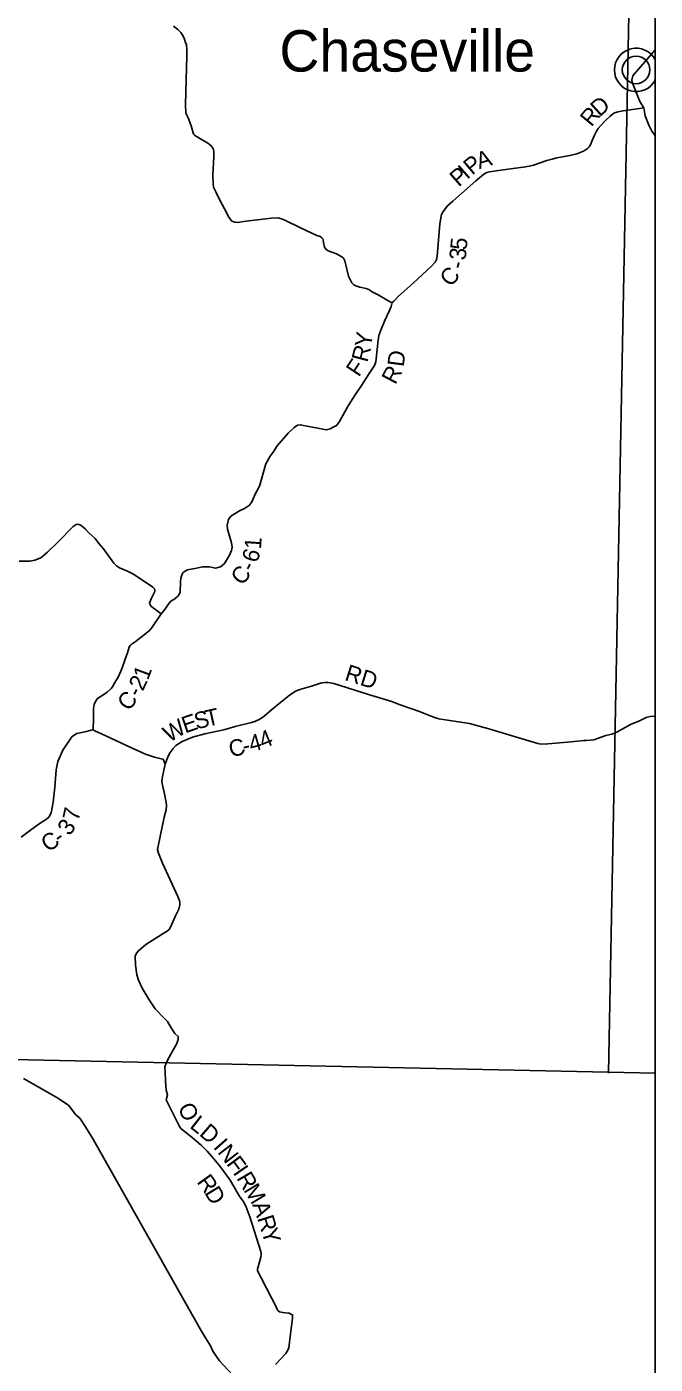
# Model space of a CAD drawing. Extents: x 0 to 34, y 0 to 22.
# Drawn here: x 28.547 to 30.697, y 13.16 to 17.734 of the extents above; entities that cross this region are included whole.
import ezdxf

# ---------------------------------------------------------------- set-up
doc = ezdxf.new("R2010")
doc.units = 0
for name, color, linetype in [('Default', 7, 'Continuous'), ('GM_X_County_Road', 7, 'Continuous'), ('GM_X_County_Road_Text', 7, 'Continuous'), ('GM_X_State_Route', 7, 'Continuous'), ('GM_X_Township', 7, 'Continuous'), ('GM_X_Unincorporated', 7, 'Continuous'), ('GM_X_Unincorporated_Text', 7, 'Continuous')]:
    doc.layers.add(name, color=color, linetype=linetype)

msp = doc.modelspace()

# ---------------------------------------------------------------- linework, layer by layer
at = {"layer": 'Default'}
msp.add_line((30.697, 20.4625), (30.697, 9.6182), dxfattribs=at)
for points in [[(30.6575, 17.4567), (30.6273, 17.4526), (30.6037, 17.4487), (30.587, 17.4467), (30.5689, 17.4432), (30.5547, 17.4384), (30.5425, 17.4286), (30.5266, 17.4132), (30.5109, 17.3964), (30.5021, 17.3859), (30.4947, 17.3746), (30.4889, 17.3637), (30.4815, 17.3453), (30.4749, 17.3302), (30.471, 17.3234), (30.4656, 17.3171), (30.4511, 17.3082), (30.4291, 17.299), (30.4051, 17.2936), (30.3733, 17.288), (30.36, 17.2855), (30.3441, 17.2811), (30.3266, 17.2768), (30.281, 17.2611), (30.2711, 17.2582), (30.2529, 17.2547), (30.1684, 17.2436), (30.1301, 17.2381), (30.1203, 17.2359), (30.11, 17.2304), (30.0832, 17.2069), (30.0047, 17.1378), (29.9863, 17.121), (29.9717, 17.1026), (29.9659, 17.0917), (29.9631, 17.0808), (29.9598, 17.0593), (29.957, 17.0191), (29.9504, 16.9492), (29.9488, 16.9382), (29.9437, 16.9284), (29.9318, 16.9153), (29.869, 16.8574), (29.8384, 16.8302), (29.8182, 16.8126), (29.8028, 16.7955), (29.7967, 16.7913), (29.7922, 16.7923), (29.7796, 16.7995), (29.7486, 16.817), (29.7264, 16.8282), (29.7189, 16.834), (29.708, 16.8383), (29.6865, 16.8431), (29.6729, 16.8482), (29.6654, 16.8517), (29.6591, 16.8583), (29.6472, 16.8807), (29.6347, 16.9339), (29.6303, 16.9431), (29.625, 16.9473), (29.607, 16.9574), (29.5784, 16.968), (29.5709, 16.9726), (29.566, 16.9799), (29.5625, 16.9958), (29.5614, 17.0045), (29.5592, 17.0091), (29.5566, 17.0126), (29.5502, 17.0164), (29.5397, 17.0196), (29.4837, 17.0468), (29.4303, 17.0729), (29.4186, 17.0776), (29.4062, 17.0804), (29.3827, 17.0796), (29.2974, 17.0693), (29.2663, 17.0648), (29.2588, 17.0652), (29.249, 17.0695), (29.2442, 17.0749), (29.2378, 17.0826), (29.2234, 17.1115), (29.2076, 17.1409), (29.1943, 17.1676), (29.1862, 17.1855), (29.1841, 17.1976), (29.1837, 17.2268), (29.1864, 17.29), (29.187, 17.307), (29.1852, 17.3139), (29.183, 17.3192), (29.1778, 17.3272), (29.1658, 17.3353), (29.1298, 17.357), (29.1223, 17.362), (29.1185, 17.3658), (29.1159, 17.3708), (29.1098, 17.3947), (29.1051, 17.4073), (29.0988, 17.4229), (29.0929, 17.4339), (29.0915, 17.4389), (29.0903, 17.4684), (29.0948, 17.635), (29.0946, 17.6426), (29.0943, 17.6562), (29.0937, 17.6725), (29.0904, 17.6805), (29.0864, 17.6915), (29.0805, 17.7037), (29.0735, 17.7144), (29.0634, 17.7248), (29.0488, 17.7363)], [(29.0798, 15.8643), (29.0799, 15.8645), (29.0807, 15.8664), (29.0868, 15.8706), (29.0969, 15.8763), (29.1279, 15.883), (29.1476, 15.8869), (29.1726, 15.8867), (29.193, 15.8827), (29.2097, 15.887), (29.2232, 15.898), (29.2408, 15.9266), (29.2471, 15.9425), (29.2501, 15.9547), (29.2477, 15.969), (29.2341, 16.0163), (29.2325, 16.0299), (29.2365, 16.0489), (29.2455, 16.0603), (29.2742, 16.0783), (29.2915, 16.086), (29.3085, 16.0982), (29.3171, 16.1093), (29.3283, 16.1355), (29.3432, 16.1628), (29.365, 16.2387), (29.3799, 16.265), (29.3897, 16.2787), (29.4039, 16.3004), (29.4407, 16.3446), (29.4621, 16.364), (29.4731, 16.3717), (29.4825, 16.3729), (29.5178, 16.3659), (29.5423, 16.3612), (29.5712, 16.3553), (29.5852, 16.3584), (29.5954, 16.365), (29.6067, 16.37), (29.6164, 16.384), (29.646, 16.4376), (29.6707, 16.4749), (29.6916, 16.5076), (29.7178, 16.5484), (29.7362, 16.5757), (29.7407, 16.5883), (29.7496, 16.6618), (29.7514, 16.6781), (29.758, 16.6967), (29.7707, 16.7267), (29.7882, 16.7636), (29.793, 16.7772), (29.7967, 16.7913)], [(28.5215, 15.9069), (28.557, 15.9064), (28.574, 15.9094), (28.5946, 15.9177), (28.6181, 15.9374), (28.6534, 15.9717), (28.7054, 16.0253), (28.7162, 16.0319), (28.7219, 16.0324), (28.7318, 16.0299), (28.7475, 16.0162), (28.7595, 16.0035), (28.7804, 15.9839), (28.7938, 15.967), (28.8095, 15.9485), (28.845, 15.8992), (28.8538, 15.8902), (28.8641, 15.8834), (28.891, 15.8719), (28.9005, 15.8678), (28.9115, 15.8622), (28.9781, 15.8176), (28.9838, 15.8115), (28.9854, 15.807), (28.9847, 15.8021), (28.9723, 15.7774), (28.9671, 15.7633), (28.9679, 15.7592), (28.9741, 15.7505), (28.9744, 15.7502)], [(29.0064, 15.7261), (29.0188, 15.7413), (29.033, 15.7615), (29.0398, 15.7691), (29.053, 15.7779), (29.0631, 15.786), (29.0688, 15.7924), (29.0717, 15.8), (29.073, 15.836), (29.0744, 15.8482), (29.077, 15.858), (29.0798, 15.8643)], [(28.9744, 15.7502), (28.9748, 15.7499), (29.0064, 15.7261), (28.9974, 15.7128), (28.9828, 15.6907), (28.9738, 15.6774), (28.9682, 15.6709), (28.949, 15.6541), (28.9174, 15.6308), (28.9038, 15.6212), (28.9008, 15.6182), (28.8971, 15.6125), (28.8915, 15.5931), (28.8822, 15.5673), (28.8737, 15.5415), (28.8693, 15.5305), (28.8592, 15.51), (28.8483, 15.4917), (28.8405, 15.4769), (28.836, 15.4708), (28.8225, 15.4586), (28.8066, 15.4486), (28.7957, 15.441), (28.7878, 15.4352), (28.7826, 15.4261), (28.7777, 15.4158), (28.7755, 15.4022), (28.7758, 15.3692), (28.7746, 15.3291), (28.7799, 15.3261), (28.8171, 15.3089), (28.9056, 15.2679), (28.9535, 15.2463), (28.9834, 15.2359), (29.0069, 15.2304), (29.0134, 15.2289), (29.0207, 15.2127), (29.0177, 15.202), (29.0108, 15.1702), (29.0094, 15.1546), (29.0106, 15.1456), (29.0177, 15.1104), (29.0239, 15.0809), (29.0244, 15.071), (29.0233, 15.0559), (29.0167, 15.0305), (28.9962, 14.9319), (28.994, 14.9205), (28.9975, 14.9073), (29.0118, 14.8733), (29.0633, 14.7593), (29.0695, 14.7449), (29.0707, 14.7389), (29.0704, 14.7313), (29.0667, 14.7161), (29.0551, 14.6918), (29.0391, 14.6549), (29.0339, 14.6469), (29.0271, 14.6408), (29.0097, 14.6312), (28.9547, 14.5956), (28.9291, 14.5743), (28.9224, 14.5659), (28.9183, 14.556), (28.9189, 14.5246), (28.9237, 14.492), (28.9287, 14.4731), (28.9414, 14.4459), (28.9652, 14.4063), (28.9859, 14.3751), (29.0171, 14.3439), (29.0282, 14.3318), (29.0405, 14.3103), (29.0535, 14.2911), (29.0648, 14.2813), (29.0648, 14.2708), (29.0607, 14.2569), (29.0299, 14.2027), (29.0228, 14.1862), (29.0196, 14.177), (29.0196, 14.1739)], [(29.0207, 15.2127), (29.0255, 15.2244), (29.0311, 15.24), (29.0371, 15.2518), (29.0472, 15.2659), (29.0573, 15.2762), (29.0784, 15.2896), (29.1143, 15.3046), (29.1566, 15.3155), (29.2212, 15.33), (29.2602, 15.3405), (29.3157, 15.3545), (29.3267, 15.358), (29.3448, 15.366), (29.3591, 15.3764), (29.3843, 15.3985), (29.4163, 15.4245), (29.4449, 15.447), (29.4664, 15.462), (29.4807, 15.4677), (29.5211, 15.4794), (29.5445, 15.4867), (29.5566, 15.4899), (29.5653, 15.4914), (29.5778, 15.4915), (29.5972, 15.4875), (29.7163, 15.4508), (29.7963, 15.426), (29.8206, 15.4163), (29.8612, 15.4022), (29.8908, 15.3922), (29.9155, 15.3822), (29.9451, 15.3706), (29.9565, 15.3669), (29.9865, 15.3622), (30.0615, 15.3514), (30.1271, 15.3329), (30.2531, 15.2959), (30.2952, 15.2833), (30.3054, 15.2811), (30.3296, 15.2813), (30.3962, 15.2874), (30.4535, 15.2926), (30.4609, 15.2933)], [(30.4609, 15.2933), (30.487, 15.2957), (30.5278, 15.3107), (30.5486, 15.3147), (30.5659, 15.3217), (30.6119, 15.3479), (30.6425, 15.36), (30.6653, 15.3715), (30.6797, 15.3755), (30.697, 15.3761)], [(29.0196, 14.1739), (29.0199, 14.1599), (29.0213, 14.128), (29.0239, 14.0976), (29.028, 14.0819), (29.0241, 14.0644), (29.0498, 14.0123), (29.0686, 13.9749), (29.0744, 13.9666), (29.0896, 13.9539), (29.1136, 13.9347), (29.1437, 13.9095), (29.1646, 13.8885), (29.1872, 13.8629), (29.2086, 13.8365), (29.243, 13.789), (29.2641, 13.7521), (29.2763, 13.7324), (29.287, 13.7177), (29.2962, 13.7011), (29.3105, 13.6641), (29.3477, 13.5454), (29.3489, 13.5375), (29.3482, 13.5257), (29.3383, 13.4927), (29.3364, 13.4855), (29.3365, 13.4798), (29.3484, 13.456), (29.403, 13.349)], [(29.403, 13.349), (29.4032, 13.3486), (29.4037, 13.3477), (29.4071, 13.3424), (29.4113, 13.3398), (29.4231, 13.3368), (29.4424, 13.3351), (29.4454, 13.3343), (29.4507, 13.3313), (29.456, 13.3291), (29.4558, 13.3177), (29.4525, 13.2904), (29.4479, 13.2555), (29.4429, 13.2165), (29.4414, 13.2104), (29.4328, 13.1971), (29.3975, 13.1589)]]:
    msp.add_lwpolyline(points, dxfattribs=at)
at = {"layer": 'GM_X_County_Road'}
msp.add_lwpolyline([(28.5275, 14.9622), (28.5597, 14.9867), (28.5772, 14.9995), (28.5967, 15.0123), (28.6146, 15.0236), (28.6224, 15.0313), (28.6301, 15.0455), (28.6374, 15.0827), (28.6426, 15.1331), (28.6476, 15.193), (28.6535, 15.2215), (28.6702, 15.2604), (28.7008, 15.3053), (28.709, 15.3119), (28.718, 15.3169), (28.7515, 15.324), (28.7674, 15.3287), (28.7746, 15.3291)], dxfattribs=at)
at = {"layer": 'GM_X_State_Route'}
for points in [[(30.697, 17.3608), (30.684, 17.379), (30.6748, 17.3977), (30.6623, 17.4289), (30.6575, 17.4567), (30.644, 17.4784), (30.6184, 17.5446), (30.617, 17.5529), (30.6208, 17.5657), (30.6252, 17.5721), (30.6461, 17.5966), (30.6621, 17.6152), (30.697, 17.6549)], [(28.536, 14.137), (28.6503, 14.0719), (28.6894, 14.0466), (28.7149, 14.0127), (28.729, 14.0011), (28.7484, 13.9724), (28.7755, 13.9274), (29.1411, 13.2784), (29.1589, 13.2504), (29.176, 13.2226), (29.1829, 13.2044), (29.2067, 13.1712), (29.251, 13.1233)]]:
    msp.add_lwpolyline(points, dxfattribs=at)
at = {"layer": 'GM_X_Township'}
for p, q in [((30.5368, 14.1558), (30.6135, 18.1642)), ((24.5006, 14.2876), (30.697, 14.1555))]:
    msp.add_line(p, q, dxfattribs=at)
at = {"layer": 'GM_X_Unincorporated'}
msp.add_circle((30.6314, 17.5864), 0.0471, dxfattribs=at)
msp.add_arc((30.6314, 17.5864), 0.0742, 27.9792, 332.0208, dxfattribs=at)

# ---------------------------------------------------------------- texts
at = {"layer": 'GM_X_County_Road_Text'}
for s, rotation, p in [('D', 42.0803, (30.5066, 17.4235)), ('R', 50.7251, (30.4786, 17.3891)), ('P', 40.0246, (30.0705, 17.2245)), ('A', 18.0444, (30.0948, 17.2464)), ('P', 41.4094, (30.0246, 17.1841)), ('I', 41.3438, (30.0533, 17.2094)), ('3', 84.8445, (30.0483, 16.934)), ('5', 84.8487, (30.0515, 16.9687)), ('-', 75.0151, (30.0405, 16.901)), ('C', 49.2539, (29.9972, 16.8413)), ('Y', 82.1193, (29.7248, 16.6359)), ('R', 75.4588, (29.7118, 16.5839)), ('D', 82.6809, (29.8363, 16.5692)), ('F', 56.555, (29.6825, 16.5337)), ('R', 62.1188, (29.8079, 16.5073)), ('1', 86.1289, (29.348, 15.9454)), ('6', 73.1837, (29.3354, 15.8982)), ('C', 50.4338, (29.2833, 15.8202)), ('-', 61.9541, (29.3198, 15.8665)), ('RD', 342.4992, (29.6314, 15.5004)), ('2', 63.873, (28.9437, 15.4598)), ('1', 69.6432, (28.9616, 15.4969)), ('C', 49.3923, (28.8941, 15.3908)), ('-', 62.5198, (28.9323, 15.4379)), ('W', 30.5301, (29.0346, 15.2849)), ('E', 18.874, (29.0884, 15.317)), ('S', 14.1999, (29.1274, 15.3304)), ('T', 12.7566, (29.1641, 15.3396)), ('4', 22.0714, (29.3551, 15.2644)), ('C', 14.4215, (29.246, 15.2347)), ('4', 15.9741, (29.3153, 15.2527)), ('-', 14.7411, (29.2915, 15.2464)), ('7', 77.0313, (28.7235, 15.015)), ('3', 54.5647, (28.6934, 14.9645)), ('C', 33.6608, (28.6196, 14.9094)), ('-', 35.8265, (28.6603, 14.9366)), ('O', 295.5501, (29.0623, 14.038)), ('L', 321.8164, (29.1014, 13.971)), ('D', 318.9416, (29.1341, 13.9452)), ('I', 311.3269, (29.1826, 13.9014)), ('N', 307.8076, (29.1974, 13.8847)), ('F', 306.8214, (29.2278, 13.8454)), ('I', 304.7401, (29.2504, 13.8153)), ('R', 300.1665, (29.2631, 13.7971)), ('R', 305.6606, (29.1268, 13.7836)), ('D', 301.1705, (29.1533, 13.7467)), ('M', 301.1074, (29.287, 13.756)), ('A', 290.1723, (29.3175, 13.7059)), ('R', 287.6462, (29.3345, 13.6597)), ('Y', 287.3682, (29.3486, 13.6154))]:
    msp.add_text(s, height=0.0567, rotation=rotation, dxfattribs=at).set_placement(p)
at = {"layer": 'GM_X_Unincorporated_Text'}
msp.add_text('Chaseville', height=0.14175, rotation=0, dxfattribs=at).set_placement((29.4112, 17.5806))

doc.saveas('drawing.dxf')
